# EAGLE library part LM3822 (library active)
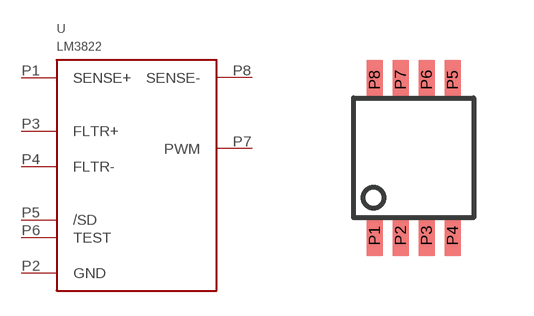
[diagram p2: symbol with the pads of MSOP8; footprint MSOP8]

Designator prefix U

## LM3822  [MSOP8]
P1  SENSE+  pwr
P2  GND  pwr
P3  FLTR+
P4  FLTR-
P5  /SD  in
P6  TEST  in
P7  PWM  out
P8  SENSE-  pwr

## Footprint MSOP8 (pad centres in mm)
smd 0.4 x 1: P1 -0.975,-1.95; P2 -0.325,-1.95; P3 0.325,-1.95; P4 0.975,-1.95; P5 0.975,1.95; P6 0.325,1.95; P7 -0.325,1.95; P8 -0.975,1.95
